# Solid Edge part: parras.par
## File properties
Username: Kasutaja
Author: Kasutaja
Template: Iso Metric Part.par
Last saved by: Kasutaja
Revision: 7
Application: Solid Edge
Accuracy: 0,990
Face Style: Model Default
Fill Style: Normal
Coef. of Thermal Exp: 0.0
Thermal Conductivity: 0.0
Specific Heat: 0.0
Modulus of Elasticity: 0.0
Poisson's Ratio: 0.0
Yield Stress: 0.0
Ultimate Stress: 0.0
Elongation: 0.0
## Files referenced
..\Raemapuu.par.asm
?C:\Users\Kasutaja\Desktop\ema asjad\New folder\Raemapuu.par.asm
C:\Users\Kasutaja\Desktop\ema asjad\New folder\Raemapuu.par
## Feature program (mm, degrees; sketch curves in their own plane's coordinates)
thicken "Thicken_10"  Distance1 = 2 mm
web network "WebNetwork_5"  Thickness = 1 mm
sketch for "unnamed Cutout 1" plane through (0, -102.0101, 0) normal (0, -1, 0) x-axis (1, 0, 0)
  circle centre (-105.6281, 81.2973) radius 3
extrude "unnamed Cutout 1" cut through along -normal
sketch for "unnamed Cutout 2" plane through (0, -102.0101, 0) normal (0, -1, 0) x-axis (1, 0, 0)
extrude "unnamed Cutout 2" cut through along -normal
sketch for "unnamed Cutout 3" plane through (0, -102.0101, 0) normal (0, -1, 0) x-axis (1, 0, 0)
extrude "unnamed Cutout 3" cut through along -normal
sketch for "unnamed Cutout 4" plane through (0, -102.0101, 0) normal (0, -1, 0) x-axis (1, 0, 0)
extrude "unnamed Cutout 4" cut through along -normal
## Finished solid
Body 1: solid body, 11 faces, 20 edges, 8 vertices.
  Faces by surface: cylinder 4, plane 3, spline 3, offset 1
  Edges by curve: intersection 12, curve on surface 5, line 2, spline 1
Body 2: sheet body, 1 face, 2 edges, 2 vertices.
  Faces by surface: spline 1
  Edges by curve: curve on surface 1, spline 1
Bounding box of the edges (mm; curved faces can reach further): 632.055 x 97.729 x 109.495, from (-275.7609, -101.7292, 5.5) to (356.294, -4.0001, 114.9947).
Cylindrical faces by radius (mm): R3 x4
Planar faces by outward normal: +y 1, +z 1, -z 1
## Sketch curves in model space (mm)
circle centre (160.7403, -102.0101, 78.5902) radius 3
circle centre (67.9065, -102.0101, 82.513) radius 3
circle centre (-31.4281, -102.0101, 80.8394) radius 3
circle centre (-105.6281, -102.0101, 81.2973) radius 3
circle centre (-194.8242, -102.0101, 83.1415) radius 3
spline (-264.251, -102.0101, 80.8394) -> (47.6406, -102.0101, 82.2383) -> (360.2962, -102.0101, 81.521)
line (-29.673, -6, 57.7839) -> (55.2383, -6, 57.7839)
spline (200, -58.4774, 106.2549) -> (200, -38.5844, 52.632) -> (200, -6, 7.5)
spline (-200, -50.622, 114.9948) -> (-200, -36.1713, 57.794) -> (-200, -6, 7.5)
spline (120.1851, -91.7869, 112.286) -> (120.1851, -61.5091, 48.2472) -> (120.1851, -6, 7.5)
spline (-117.4118, -84.7171, 112.6364) -> (-117.4118, -60.0628, 51.7347) -> (-117.4118, -6, 7.5)
spline (0, -100.6182, 112.3445) -> (0, -61.7634, 43.4502) -> (0, -6, 7.5)
arc centre (200, -6, 176.323) radius 168.823 from (356.294, -6, 112.5) through (294.1446, -6, 36.1874) to (200, -6, 7.5)
line (200, -6, 7.5) -> (-200, -6, 7.5)
arc centre (-200, -6, 83.2634) radius 75.7634 from (-200, -6, 7.5) through (-264.291, -6, 43.179) to (-269.895, -6, 112.5)
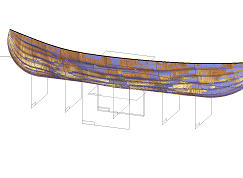
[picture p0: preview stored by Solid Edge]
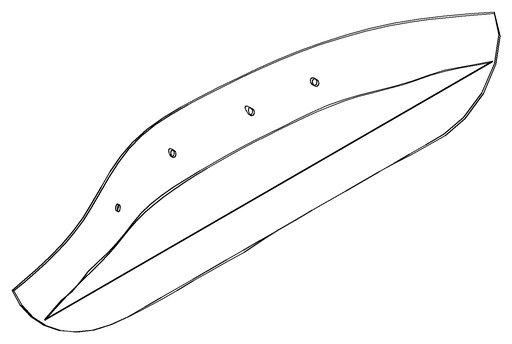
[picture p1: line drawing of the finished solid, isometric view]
